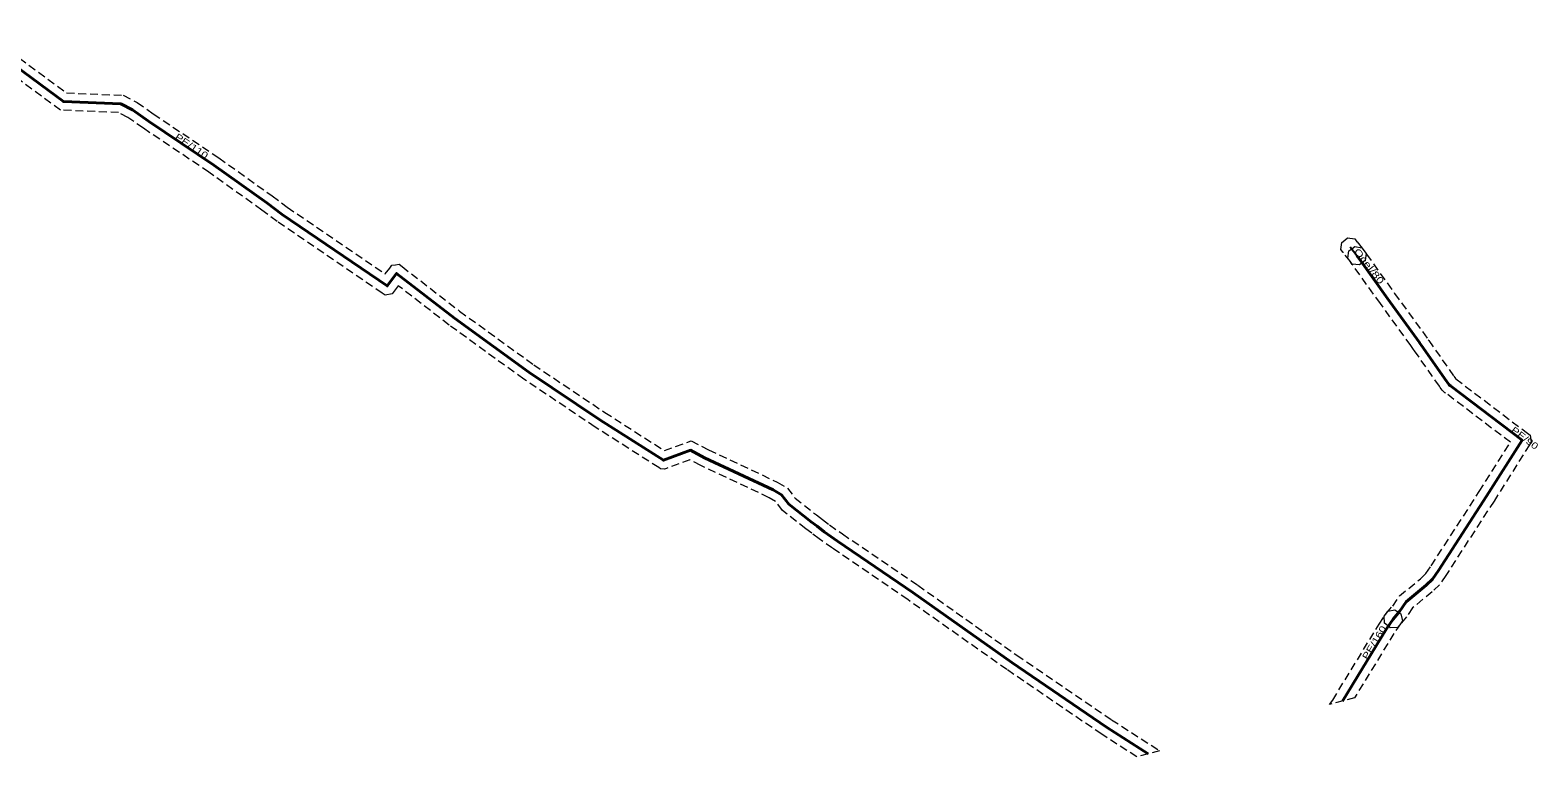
# Model space of a CAD drawing. Extents: x -601345 to -601001, y -1004225 to -1003815.
# Drawn here: x -601172.9 to -601000.6, y -1004225 to -1004142 of the extents above; entities that cross this region are included whole.
import ezdxf

# ---------------------------------------------------------------- set-up
doc = ezdxf.new("R2010")
doc.units = 0
doc.header["$LTSCALE"] = 0.3
doc.linetypes.add('MEDIUM_DASHED', pattern=[4.5, 3, -1.5])
doc.layers.add('1', color=7, linetype='MEDIUM_DASHED', lineweight=13)
doc.layers.add('24', color=7, linetype='Continuous', lineweight=25)
doc.layers.add('30', color=7, linetype='Continuous')

msp = doc.modelspace()

# ---------------------------------------------------------------- linework, layer by layer
at = {"layer": '1'}
for points in [[(-601178.448, -1004141.982), (-601168.713, -1004149.153), (-601162.224, -1004149.42), (-601160.659, -1004150.244), (-601158.795, -1004151.545), (-601151.31, -1004156.568), (-601145.231, -1004160.922), (-601143.49, -1004162.215), (-601132.301, -1004169.839), (-601131.796, -1004169.175), (-601131.544, -1004168.843), (-601131.131, -1004168.789), (-601130.717, -1004168.734), (-601130.388, -1004168.989), (-601123.81, -1004174.08), (-601115.338, -1004180.22), (-601107.233, -1004185.653), (-601100.401, -1004190.01), (-601097.358, -1004188.887), (-601095.374, -1004189.935), (-601087.526, -1004193.623), (-601086.368, -1004194.293), (-601085.483, -1004195.442), (-601083.052, -1004197.366), (-601082.365, -1004197.874), (-601081.556, -1004198.505), (-601080.073, -1004199.536)], [(-601049.348, -1004220.766), (-601043.848, -1004224.303), (-601046.448, -1004225.009), (-601050.452, -1004222.434), (-601061.3, -1004215.042), (-601072.62, -1004207.041), (-601081.207, -1004201.184), (-601082.744, -1004200.115), (-601083.575, -1004199.466), (-601084.268, -1004198.954), (-601086.917, -1004196.858), (-601087.712, -1004195.827), (-601088.454, -1004195.397), (-601096.266, -1004191.725), (-601097.502, -1004191.073), (-601100.174, -1004192.058), (-601100.394, -1004192.139), (-601100.86, -1004192.089), (-601101.058, -1004191.963), (-601108.327, -1004187.327), (-601116.482, -1004181.86), (-601125.01, -1004175.68), (-601130.815, -1004171.188), (-601131.284, -1004171.805), (-601131.526, -1004172.123), (-601132.313, -1004172.251), (-601132.643, -1004172.026), (-601144.65, -1004163.845), (-601146.409, -1004162.538), (-601152.45, -1004158.212), (-601159.925, -1004153.195), (-601161.701, -1004151.956), (-601162.756, -1004151.4), (-601169.407, -1004151.127), (-601179.652, -1004143.578)], [(-601080.073, -1004199.536), (-601071.48, -1004205.399), (-601060.16, -1004213.398), (-601049.348, -1004220.766)]]:
    msp.add_lwpolyline(points, dxfattribs=at)
for points in [[(-601021.846, -1004168.71), (-601022.1, -1004168.383), (-601022.86, -1004167.403), (-601022.88, -1004167.377), (-601023.134, -1004167.05), (-601023.032, -1004166.228), (-601022.705, -1004165.974), (-601022.378, -1004165.72), (-601021.556, -1004165.822), (-601021.302, -1004166.149), (-601021.28, -1004166.177), (-601020.52, -1004167.157), (-601020.266, -1004167.484), (-601020.37, -1004168.306), (-601020.697, -1004168.56), (-601021.024, -1004168.814)], [(-601015.16, -1004178.017), (-601015.16, -1004178.005), (-601018.621, -1004173.225), (-601021.842, -1004168.743), (-601022.122, -1004168.353), (-601022.364, -1004168.017), (-601022.23, -1004167.199), (-601021.893, -1004166.958), (-601021.557, -1004166.716), (-601020.739, -1004166.85), (-601020.498, -1004167.187), (-601020.218, -1004167.577), (-601016.999, -1004172.055), (-601013.16, -1004177.356), (-601013.16, -1004177.377), (-601013.111, -1004177.442), (-601010.252, -1004181.508), (-601010.137, -1004181.672), (-601010.061, -1004181.783), (-601010.01, -1004181.823), (-601001.835, -1004188.034), (-601001.525, -1004188.269), (-601001.387, -1004189.035), (-601001.595, -1004189.364), (-601005.648, -1004195.779), (-601011.158, -1004204.274), (-601011.893, -1004205.35), (-601012.724, -1004206.147), (-601014.944, -1004207.99), (-601015.636, -1004209.001), (-601016.423, -1004209.913), (-601016.693, -1004210.227), (-601017.519, -1004210.287), (-601017.833, -1004210.017), (-601018.147, -1004209.747), (-601018.207, -1004208.921), (-601017.937, -1004208.607), (-601017.224, -1004207.779), (-601016.436, -1004206.63), (-601014.056, -1004204.653), (-601013.427, -1004204.05), (-601012.822, -1004203.166), (-601007.332, -1004194.701), (-601003.775, -1004189.071), (-601011.149, -1004183.47), (-601011.281, -1004183.413), (-601011.564, -1004183.13), (-601011.783, -1004182.808), (-601011.888, -1004182.658), (-601014.729, -1004178.618), (-601014.849, -1004178.458)], [(-601017.088, -1004210.919), (-601021.568, -1004218.252), (-601024.433, -1004219.03), (-601024.077, -1004218.522), (-601018.772, -1004209.841), (-601018.011, -1004208.704), (-601017.78, -1004208.36), (-601016.968, -1004208.199), (-601016.624, -1004208.429), (-601016.28, -1004208.66), (-601016.119, -1004209.472), (-601016.349, -1004209.816)]]:
    msp.add_lwpolyline(points, close=True, dxfattribs=at)
at = {"layer": '24', "lineweight": 40}
for points in [[(-601045.148, -1004224.656), (-601049.9, -1004221.6), (-601060.73, -1004214.22), (-601072.05, -1004206.22), (-601080.64, -1004200.36), (-601082.15, -1004199.31), (-601082.97, -1004198.67), (-601083.66, -1004198.16), (-601086.2, -1004196.15), (-601087.04, -1004195.06), (-601087.99, -1004194.51), (-601095.82, -1004190.83), (-601097.43, -1004189.98), (-601100.52, -1004191.12), (-601107.78, -1004186.49), (-601115.91, -1004181.04), (-601124.41, -1004174.88), (-601131, -1004169.78), (-601132.08, -1004171.2), (-601144.07, -1004163.03), (-601145.82, -1004161.73), (-601151.88, -1004157.39), (-601159.36, -1004152.37), (-601161.18, -1004151.1), (-601162.49, -1004150.41), (-601169.06, -1004150.14), (-601179.05, -1004142.78)], [(-601017.18, -1004209.26), (-601016.43, -1004208.39), (-601015.69, -1004207.31), (-601013.39, -1004205.4), (-601012.66, -1004204.7), (-601011.99, -1004203.72), (-601006.49, -1004195.24), (-601002.44, -1004188.83), (-601010.618, -1004182.617), (-601010.64, -1004182.6), (-601010.71, -1004182.57), (-601010.79, -1004182.49), (-601010.96, -1004182.24), (-601011.07, -1004182.083), (-601013.92, -1004178.03), (-601014.04, -1004177.87), (-601014.16, -1004177.7), (-601014.16, -1004177.68), (-601017.81, -1004172.64), (-601021.03, -1004168.16), (-601021.31, -1004167.77)], [(-601017.18, -1004209.26), (-601017.93, -1004210.38), (-601022.973, -1004218.634)]]:
    msp.add_lwpolyline(points, dxfattribs=at)
at = {"layer": '24'}
msp.add_lwpolyline([(-601021.31, -1004167.77), (-601022.07, -1004166.79), (-601022.091, -1004166.763)], dxfattribs=at)

# ---------------------------------------------------------------- texts
at = {"layer": '30'}
for s, rotation, width, p in [('PE/110', 326.134, 1.3, (-601156.404, -1004154.353)), ('Ocel/80', 307.794, 1.4, (-601021.7, -1004167.266)), ('PE/90', 322.775, 1.3, (-601003.773, -1004187.817)), ('PE/160', 58.573, 1.3, (-601020.126, -1004213.974))]:
    msp.add_text(s, height=0.75, rotation=rotation, dxfattribs=dict(at, width=width)).set_placement(p)

doc.saveas('drawing.dxf')
